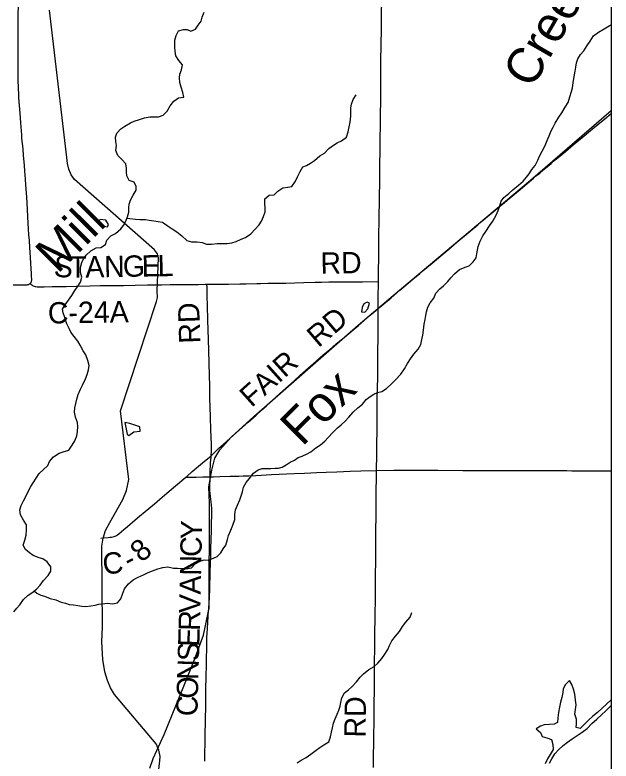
# Model space of a CAD drawing. Extents: x -87 to 2145, y -2128 to 440.
# Drawn here: x 188.3 to 230.2, y -1010.1 to -957.6 of the extents above; entities that cross this region are included whole.
import ezdxf

# ---------------------------------------------------------------- set-up
doc = ezdxf.new("R2010")
doc.units = 0
for name, color, linetype in [('GM_X_County_Road', 7, 'Continuous'), ('GM_X_County_Road_Text', 7, 'Continuous'), ('GM_X_Minor_Lake', 7, 'Continuous'), ('GM_X_Minor_River', 7, 'Continuous'), ('GM_X_Minor_River_Text', 7, 'Continuous'), ('GM_X_Rail_Line', 7, 'Continuous'), ('GM_X_Township_Road', 7, 'Continuous'), ('SC_Scratch1', 7, 'Continuous')]:
    doc.layers.add(name, color=color, linetype=linetype)

msp = doc.modelspace()

# ---------------------------------------------------------------- linework, layer by layer
at = {"layer": 'GM_X_County_Road'}
msp.add_line((201.805, -988.806), (202.068, -988.593), dxfattribs=at)
for points in [[(188.544, -963.408), (188.537, -963.299), (188.505, -962.628), (188.492, -962.268), (188.484, -961.793), (188.484, -960.76), (188.485, -960.186), (188.486, -959.497), (188.49, -958.825), (188.499, -957.955), (188.525, -956.578), (188.537, -955.659), (188.538, -955.627)], [(189.333, -976.48), (189.354, -976.459), (189.377, -976.432), (189.398, -976.405), (189.414, -976.374), (189.426, -976.344), (189.434, -976.311), (189.438, -976.284), (189.44, -976.25), (189.441, -976.213), (189.441, -976.158), (189.439, -976.004), (189.429, -975.765), (189.383, -975.076), (189.354, -974.619), (189.314, -973.947), (189.276, -973.456), (189.246, -973.047), (189.222, -972.622), (189.201, -972.246), (189.175, -971.771), (189.119, -970.804), (189.094, -970.411), (189.056, -969.806), (189.037, -969.544), (189.006, -969.135), (188.958, -968.563), (188.925, -968.187), (188.87, -967.451), (188.837, -967.042), (188.811, -966.797), (188.778, -966.471), (188.758, -966.259), (188.74, -966.014), (188.674, -965.164), (188.621, -964.493), (188.583, -963.954), (188.544, -963.408)], [(213.812, -978.237), (213.915, -978.151), (214.343, -977.793), (214.443, -977.709), (214.718, -977.475), (215.338, -976.938), (215.602, -976.718), (216.251, -976.165), (216.731, -975.768), (216.97, -975.568), (217.603, -975.046), (218.205, -974.539), (218.766, -974.059), (219.346, -973.577), (219.734, -973.248), (220.817, -972.346), (221.079, -972.123), (221.625, -971.651), (221.889, -971.43), (222.208, -971.173), (222.693, -970.782), (222.881, -970.624), (223.146, -970.404), (223.535, -970.077), (223.786, -969.867), (224.149, -969.559), (224.726, -969.074), (224.95, -968.882), (225.164, -968.703), (225.464, -968.447), (225.964, -968.023), (226.254, -967.783), (226.582, -967.51), (226.971, -967.183), (227.529, -966.725), (228.161, -966.202), (228.877, -965.601), (229.242, -965.297), (229.738, -964.893), (230.183, -964.524)], [(188.147, -976.569), (188.443, -976.566), (188.77, -976.571), (188.985, -976.573), (189.033, -976.572), (189.083, -976.569), (189.132, -976.563), (189.173, -976.557), (189.21, -976.549), (189.241, -976.538), (189.272, -976.524), (189.299, -976.508), (189.333, -976.48)], [(189.333, -976.48), (189.39, -976.529), (189.446, -976.577), (189.5, -976.614), (189.554, -976.641), (189.611, -976.663), (189.679, -976.683), (189.736, -976.694), (189.819, -976.705), (189.985, -976.714), (190.314, -976.712), (190.889, -976.697), (191.478, -976.685), (191.856, -976.677), (192.56, -976.654), (193.545, -976.638), (194.25, -976.625), (195.102, -976.617), (195.906, -976.606), (196.725, -976.594), (197.594, -976.577), (198.02, -976.569), (198.578, -976.564), (199.169, -976.551), (200.232, -976.548), (201.168, -976.541), (201.643, -976.534), (201.766, -976.533)], [(201.766, -976.533), (201.938, -976.531), (203.07, -976.515), (203.283, -976.514), (204.087, -976.506), (204.513, -976.496), (205.266, -976.477), (205.528, -976.472), (206.037, -976.462), (207.316, -976.442), (207.923, -976.432), (208.579, -976.416), (209.379, -976.389), (209.823, -976.375), (210.332, -976.368), (211.168, -976.369), (211.726, -976.367), (212.021, -976.364), (212.71, -976.35), (213.834, -976.338)], [(202.068, -988.593), (202.079, -988.241), (202.076, -987.785), (202.039, -986.769), (202.02, -985.883), (201.997, -985.162), (201.98, -984.555), (201.96, -983.653), (201.944, -982.964), (201.918, -982.056), (201.89, -981.197), (201.869, -980.409), (201.831, -979.064), (201.802, -978.015), (201.782, -977.359), (201.77, -976.732), (201.766, -976.533)], [(213.812, -978.237), (213.809, -977.884), (213.812, -977.556), (213.834, -976.338)], [(202.068, -988.593), (202.179, -988.486), (202.438, -988.215), (202.602, -988.056), (202.896, -987.795), (203.398, -987.348), (204.026, -986.795), (204.654, -986.242), (205.216, -985.738), (205.607, -985.388), (205.961, -985.071), (206.35, -984.718), (206.898, -984.224), (207.505, -983.673), (207.924, -983.305), (208.32, -982.935), (208.904, -982.409), (209.448, -981.934), (209.944, -981.505), (210.379, -981.131), (210.856, -980.73), (211.43, -980.24), (212.049, -979.729), (212.417, -979.426), (213.252, -978.712), (213.501, -978.499), (213.812, -978.237)], [(213.693, -989.623), (213.703, -988.492), (213.717, -987.672), (213.727, -986.934), (213.728, -986.442), (213.729, -986.049), (213.729, -985.492), (213.737, -985.001), (213.743, -984.542), (213.755, -983.902), (213.778, -983), (213.784, -982.344), (213.784, -981.491), (213.788, -981.032), (213.796, -980.492), (213.803, -979.983), (213.804, -979.508), (213.807, -979.131), (213.812, -978.237)], [(200.291, -990.095), (200.34, -990.054), (200.737, -989.712), (201.167, -989.333), (201.582, -988.986), (201.805, -988.806)], [(201.99, -990.075), (202, -989.603), (202.012, -989.277), (202.027, -989.081), (202.047, -988.886), (202.059, -988.725), (202.068, -988.593)], [(213.48, -1010.519), (213.489, -1009.748), (213.504, -1008.732), (213.511, -1008.098), (213.518, -1007.452), (213.534, -1005.992), (213.537, -1005.123), (213.55, -1003.582), (213.557, -1003.122), (213.573, -1002.138), (213.579, -1001.105), (213.589, -999.99), (213.608, -998.448), (213.617, -997.267), (213.635, -995.725), (213.652, -993.626), (213.659, -993.068), (213.667, -992.396), (213.675, -991.576), (213.693, -989.623)], [(194.312, -994.385), (194.458, -994.373), (194.815, -994.34), (194.943, -994.325), (195.065, -994.309), (195.149, -994.292), (195.23, -994.27), (195.303, -994.242), (195.408, -994.194), (195.479, -994.153), (195.558, -994.095), (195.757, -993.923), (195.919, -993.786), (196.182, -993.563), (196.718, -993.106), (197.02, -992.854), (197.422, -992.517), (198.074, -991.968), (198.464, -991.643), (198.955, -991.233), (199.561, -990.707), (200.291, -990.095)], [(201.608, -1010.075), (201.625, -1009.321), (201.63, -1009.009), (201.638, -1008.55), (201.651, -1007.96), (201.654, -1007.533), (201.661, -1007.041), (201.676, -1006.304), (201.688, -1005.723), (201.691, -1005.615), (201.698, -1005.205), (201.722, -1003.959), (201.74, -1003.451), (201.741, -1003.09), (201.742, -1002.729), (201.746, -1002.275), (201.754, -1001.851), (201.769, -1001.46), (201.791, -1001.002), (201.799, -1000.821), (201.807, -1000.625), (201.817, -1000.428), (201.861, -999.804), (201.894, -999.307), (201.919, -998.975), (201.94, -998.58), (201.964, -997.912), (201.996, -996.812), (202.02, -996.156), (202.031, -995.598), (202.042, -995.041), (202.059, -994.549), (202.082, -993.779), (202.095, -993.198), (202.099, -992.942), (202.107, -992.523), (202.103, -992.293), (202.09, -992.07), (202.066, -991.844), (202.016, -991.468), (201.993, -991.24), (201.979, -991.012), (201.974, -990.734), (201.988, -990.21), (201.99, -990.075)]]:
    msp.add_lwpolyline(points, dxfattribs=at)
at = {"layer": 'GM_X_Minor_Lake'}
for points in [[(194.646, -972.032), (194.248, -971.964), (194.049, -972.208), (194.432, -972.424)], [(194.432, -972.424), (194.771, -972.496), (194.837, -972.327), (194.646, -972.032)], [(213.072, -978.249), (213.206, -977.871), (213.038, -977.795), (212.793, -977.917), (212.674, -978.164)], [(212.674, -978.164), (212.623, -978.464), (212.874, -978.483), (213.072, -978.249)], [(195.986, -986.266), (196.164, -987.083), (196.282, -987.158), (196.622, -986.908), (197.058, -986.874)], [(197.058, -986.874), (197.055, -986.561), (196.351, -986.325), (195.986, -986.266)], [(230.183, -1005.77), (230.175, -1005.777), (229.874, -1006.038), (229.562, -1006.359), (229.24, -1006.659), (228.91, -1006.909), (228.599, -1007.2), (228.349, -1007.463), (228.007, -1007.773), (227.738, -1007.713), (227.757, -1007.462), (227.759, -1007.12), (227.631, -1006.763), (227.693, -1006.433), (227.724, -1006.122), (227.676, -1005.778), (227.631, -1005.354), (227.533, -1005.009), (227.414, -1004.682), (227.253, -1004.415), (226.972, -1004.677), (226.811, -1004.993), (226.782, -1005.243), (226.719, -1005.603), (226.637, -1005.933), (226.554, -1006.282), (226.481, -1006.662), (226.448, -1007.033), (226.426, -1007.354), (226.171, -1007.486), (225.85, -1007.495), (225.477, -1007.522), (225.223, -1007.613), (224.926, -1007.804), (225.228, -1008.056), (225.348, -1008.352), (225.666, -1008.444), (225.993, -1008.556), (226.081, -1008.902), (226.118, -1009.265), (225.905, -1009.61), (225.714, -1009.905), (225.541, -1010.271)], [(225.844, -1010.221), (226.015, -1009.906), (226.238, -1009.571), (226.489, -1009.278), (226.811, -1008.968), (227.13, -1008.748), (227.459, -1008.518), (227.789, -1008.278), (228.149, -1008.029), (228.499, -1007.77), (228.842, -1007.44), (229.174, -1007.12), (229.506, -1006.82), (229.807, -1006.539), (230.077, -1006.277), (230.183, -1006.167)]]:
    msp.add_lwpolyline(points, dxfattribs=at)
at = {"layer": 'GM_X_Minor_River'}
for points in [[(197.691, -1016.369), (198.446, -1010.055), (198.467, -1009.744), (198.372, -1009.308), (198.197, -1008.859), (195.258, -1005.391), (194.994, -1004.919), (194.761, -1004.407), (194.582, -1003.797), (194.452, -1002.926), (194.365, -1001.685), (194.423, -1000.62), (194.371, -994.961), (194.462, -994.38), (194.632, -993.843), (194.942, -993.3), (195.862, -991.663), (196.115, -991.027), (196.273, -990.258), (195.68, -985.445), (198.209, -977.744), (198.279, -977.455), (198.276, -976.981), (198.357, -974.659), (198.287, -974.384), (198.076, -974.105), (192.45, -969.161), (192.21, -968.84), (192.054, -968.442), (191.968, -968.026), (191.922, -967.612), (190.702, -957.239)], [(192.884, -983.905), (193.005, -983.617), (193.22, -983.192), (193.332, -982.874), (193.433, -982.555), (193.474, -982.245), (193.386, -981.899), (193.26, -981.502), (193.06, -981.203), (192.862, -980.823), (192.682, -980.525), (192.423, -980.193), (192.203, -979.894), (192.081, -979.638), (191.922, -979.32), (191.777, -978.872), (191.648, -978.535), (191.607, -978.271), (191.798, -977.976), (192.041, -977.653), (192.273, -977.329), (192.486, -976.974), (192.656, -976.699), (192.878, -976.384), (192.971, -976.035), (192.872, -975.71), (192.884, -975.358), (192.967, -975.008), (193.076, -974.751), (193.276, -974.476), (193.598, -974.185), (193.967, -973.967), (194.299, -973.939), (194.637, -973.74), (194.728, -973.431), (195.01, -973.129), (195.337, -972.949), (195.709, -972.641), (195.909, -972.386), (196.048, -972.129), (196.181, -971.792), (196.282, -971.463), (196.264, -971.141), (196.293, -970.89), (196.383, -970.611), (196.566, -970.255), (196.798, -969.922), (196.798, -969.65), (196.658, -969.353), (196.301, -969.229), (196.132, -968.901), (196.112, -968.618), (196.1, -968.366), (196.071, -968.053), (195.791, -967.751), (195.5, -967.469), (195.351, -967.121), (195.414, -966.771), (195.363, -966.497), (195.334, -966.184), (195.434, -965.906), (195.716, -965.594), (195.984, -965.412), (196.383, -965.185), (196.648, -965.064), (197.014, -964.946), (197.379, -964.828), (197.743, -964.741), (198.094, -964.763), (198.355, -964.743), (198.69, -964.634), (198.961, -964.362), (199.185, -963.977), (199.447, -963.654), (199.767, -963.404), (200.13, -963.357), (200.071, -963.033), (199.953, -962.676), (199.865, -962.331), (199.826, -962.007), (199.855, -961.756), (199.987, -961.439), (200.049, -961.099), (199.779, -960.797), (199.569, -960.468), (199.521, -960.124), (199.51, -959.871), (199.499, -959.609), (199.518, -959.348), (199.6, -959.019), (199.772, -958.703), (200.117, -958.605), (200.377, -958.614), (200.634, -958.724), (200.961, -958.575), (201.151, -958.31), (201.351, -958.025), (201.422, -957.735), (201.565, -957.378)], [(216.614, -981.104), (216.797, -980.758), (216.88, -980.409), (216.95, -980.12), (217.003, -979.769), (217.048, -979.338), (217.119, -979.018), (217.159, -978.738), (217.209, -978.478), (217.29, -978.149), (217.452, -977.832), (217.715, -977.5), (217.867, -977.153), (218.149, -976.841), (218.408, -976.629), (218.709, -976.337), (218.909, -976.073), (219.18, -975.791), (219.521, -975.501), (219.919, -975.324), (220.213, -975.234), (220.484, -974.941), (220.704, -974.678), (220.744, -974.397), (220.794, -974.127), (220.843, -973.867), (220.976, -973.509), (221.17, -973.134), (221.382, -972.809), (221.637, -972.416), (221.869, -972.082), (222.114, -971.678), (222.246, -971.34), (222.358, -971.022), (222.46, -970.694), (222.64, -970.428), (222.991, -970.139), (223.281, -969.898), (223.674, -969.559), (223.994, -969.289), (224.225, -969.005), (224.425, -968.751), (224.616, -968.446), (224.836, -968.182), (225.04, -967.806), (225.15, -967.519), (225.344, -967.163), (225.538, -966.777), (225.701, -966.421), (225.823, -966.093), (225.976, -965.736), (226.106, -965.469), (226.256, -965.192), (226.502, -964.768), (226.723, -964.464), (226.967, -964.08), (227.16, -963.745), (227.274, -963.346), (227.397, -962.978), (227.467, -962.719), (227.509, -962.368), (227.571, -962.048), (227.648, -961.548), (227.699, -961.248), (227.75, -960.947), (227.84, -960.679), (228.031, -960.374), (228.261, -960.1), (228.505, -959.726), (228.707, -959.421), (228.95, -959.057), (229.301, -958.788), (229.691, -958.55), (230.058, -958.362), (230.183, -958.28)], [(196.149, -971.873), (196.337, -971.898), (196.737, -971.943), (197.057, -971.964), (197.448, -971.978), (197.708, -972.018), (198.027, -972.06), (198.347, -972.112), (198.636, -972.172), (198.969, -972.406), (199.312, -972.629), (199.656, -972.843), (200.007, -973.118), (200.347, -973.452), (200.675, -973.544), (201.086, -973.539), (201.425, -973.602), (201.723, -973.703), (202.093, -973.716), (202.476, -973.67), (202.838, -973.672), (203.189, -973.655), (203.522, -973.607), (203.816, -973.527), (204.183, -973.369), (204.478, -973.248), (204.859, -972.98), (205.141, -972.668), (205.443, -972.357), (205.603, -972.081), (205.744, -971.774), (205.856, -971.436), (205.857, -971.133), (205.846, -970.881), (205.828, -970.528), (206.138, -970.268), (206.491, -970.24), (206.751, -969.978), (207.1, -969.749), (207.463, -969.701), (207.726, -969.65), (208, -969.278), (208.141, -968.961), (208.315, -968.594), (208.507, -968.259), (208.761, -968.168), (209.048, -968.007), (209.325, -967.825), (209.708, -967.507), (210.036, -967.297), (210.348, -966.976), (210.658, -966.746), (210.914, -966.574), (211.23, -966.434), (211.571, -966.175), (211.694, -965.797), (211.777, -965.457), (211.839, -965.117), (211.873, -964.706), (211.873, -964.424), (211.894, -964.112), (211.933, -963.852), (212.045, -963.534), (212.247, -963.209)], [(189.627, -998.087), (189.81, -998.27), (190.096, -998.401), (190.354, -998.481), (190.74, -998.635), (191.128, -998.72), (191.524, -998.885), (191.822, -998.966), (192.08, -999.046), (192.38, -999.087), (192.68, -999.118), (192.969, -999.179), (193.259, -999.189), (193.611, -999.162), (193.904, -999.102), (194.168, -999.041), (194.42, -998.999), (194.752, -998.961), (195.132, -999.005), (195.486, -998.937), (195.706, -998.663), (195.828, -998.325), (195.962, -997.948), (196.245, -997.595), (196.566, -997.315), (196.893, -997.156), (197.301, -996.959), (197.638, -996.81), (197.943, -996.68), (198.309, -996.552), (198.674, -996.445), (199.026, -996.417), (199.424, -996.512), (199.705, -996.512), (200.047, -996.514), (200.418, -996.518), (200.69, -996.467), (200.931, -996.194), (201.279, -996.005), (201.563, -995.904), (201.843, -995.935), (202.229, -995.808), (202.494, -995.676), (202.734, -995.423), (202.905, -995.137), (203.095, -994.872), (203.219, -994.474), (203.288, -994.215), (203.443, -993.828), (203.596, -993.471), (203.72, -993.073), (203.732, -992.731), (203.784, -992.391), (203.906, -992.063), (204.069, -991.706), (204.18, -991.408), (204.26, -991.129), (204.332, -990.8), (204.524, -990.464), (204.734, -990.21), (205.038, -989.829), (205.378, -989.589), (205.642, -989.488), (205.893, -989.487), (206.265, -989.48), (206.556, -989.47), (206.807, -989.469), (207.06, -989.408), (207.347, -989.237), (207.614, -989.055), (207.911, -988.895), (208.178, -988.723), (208.463, -988.613), (208.81, -988.454), (209.065, -988.312), (209.416, -988.043), (209.755, -987.834), (210.045, -987.562), (210.285, -987.309), (210.618, -986.959), (210.941, -986.628), (211.199, -986.416), (211.48, -986.154), (211.75, -985.872), (212.054, -985.521), (212.375, -985.23), (212.715, -984.971), (212.958, -984.647), (213.236, -984.426), (213.493, -984.264), (213.758, -984.152), (214.072, -984.063), (214.4, -983.863), (214.733, -983.533), (215.024, -983.252), (215.389, -982.852), (215.653, -982.469), (215.857, -982.094), (216.069, -981.779), (216.311, -981.446), (216.614, -981.104)], [(188.188, -999.58), (188.388, -999.326), (188.607, -999.072), (188.861, -998.699), (189.193, -998.399), (189.45, -998.227), (189.78, -997.967), (190.04, -997.694), (190.262, -997.38), (190.606, -997.02), (190.778, -996.704), (190.778, -996.402), (190.54, -996.061), (190.236, -995.849), (189.968, -995.769), (189.552, -995.603), (189.278, -995.422), (188.995, -995.18), (188.845, -994.893), (188.958, -994.525), (189.06, -994.186), (189.084, -993.804), (189.086, -993.462), (188.877, -993.122), (188.659, -992.752), (188.602, -992.388), (188.702, -992.099), (188.875, -991.763), (189.036, -991.467), (189.199, -991.101), (189.391, -990.765), (189.551, -990.499), (189.754, -990.164), (189.976, -989.85), (190.256, -989.578), (190.568, -989.277), (190.698, -989), (190.97, -988.668), (191.371, -988.42), (191.655, -988.32), (192.051, -988.193), (192.284, -987.839), (192.475, -987.534), (192.608, -987.197), (192.669, -986.887), (192.681, -986.535), (192.671, -986.253), (192.514, -985.874), (192.446, -985.52), (192.466, -985.228), (192.537, -984.919), (192.618, -984.62), (192.7, -984.281), (192.884, -983.905)], [(211.717, -1005.057), (211.986, -1004.825), (212.288, -1004.504), (212.54, -1004.18), (212.77, -1003.927), (213.142, -1003.628), (213.521, -1003.41), (213.78, -1003.188), (214.072, -1002.856), (214.273, -1002.562), (214.486, -1002.217), (214.606, -1001.94), (214.768, -1001.623), (215.03, -1001.29), (215.303, -1000.948), (215.526, -1000.604), (215.758, -1000.29), (216.051, -999.948), (216.183, -999.621)], [(208.114, -1010.191), (208.391, -1010.01), (208.75, -1009.812), (209.078, -1009.592), (209.45, -1009.313), (209.707, -1009.121), (209.985, -1008.93), (210.344, -1008.711), (210.456, -1008.363), (210.528, -1008.044), (210.599, -1007.744), (210.67, -1007.415), (210.772, -1007.106), (210.924, -1006.77), (211.034, -1006.502), (211.134, -1006.213), (211.183, -1005.953), (211.246, -1005.614), (211.448, -1005.269), (211.717, -1005.057)]]:
    msp.add_lwpolyline(points, dxfattribs=at)
at = {"layer": 'GM_X_Rail_Line'}
msp.add_lwpolyline([(197.758, -1010.567), (197.975, -1009.888), (198.759, -1008.214), (200.145, -1004.81), (200.881, -1002.93), (201.512, -1001.219), (201.915, -999.311), (201.947, -991.924), (201.887, -990.775), (202.11, -989.608), (202.328, -988.757), (202.675, -988.171), (203.476, -987.295), (205.067, -985.833), (212.409, -979.406), (214.858, -977.33), (224.526, -969.206), (230.183, -964.298)], dxfattribs=at)
at = {"layer": 'GM_X_Township_Road'}
for points in [[(213.984, -963.146), (213.993, -961.828), (214.004, -960.926), (214.026, -959.598), (214.035, -958.679), (214.05, -957.465), (214.058, -956.645), (214.073, -955.697)], [(213.834, -976.338), (213.838, -975.736), (213.843, -974.539), (213.859, -973.374), (213.88, -971.734), (213.892, -970.684), (213.916, -969.028), (213.932, -967.863), (213.936, -967.388), (213.944, -966.732), (213.955, -966.043), (213.965, -965.568), (213.968, -964.764), (213.982, -963.435), (213.984, -963.146)], [(201.99, -990.075), (202.229, -990.072), (202.663, -990.053), (203.408, -990.03), (203.723, -990.025), (204.017, -990.022), (204.312, -990.016), (204.722, -990.002), (205.197, -989.981), (206.31, -989.908), (206.85, -989.881), (207.358, -989.867), (207.898, -989.843), (208.617, -989.816), (209.075, -989.8), (209.501, -989.782), (210.14, -989.758), (210.894, -989.723), (211.845, -989.688), (212.582, -989.656), (213.693, -989.623)], [(213.693, -989.623), (214.91, -989.614), (215.812, -989.615), (216.533, -989.617), (217.238, -989.616), (218.009, -989.618), (219.764, -989.625), (220.814, -989.627), (221.585, -989.629), (222.569, -989.63), (223.586, -989.634), (225.095, -989.639), (226.013, -989.641), (226.669, -989.641), (227.063, -989.642), (227.423, -989.645), (228.145, -989.648), (228.834, -989.653), (229.982, -989.658), (230.183, -989.659)], [(200.291, -990.095), (201.014, -990.093), (201.478, -990.084), (201.99, -990.075)]]:
    msp.add_lwpolyline(points, dxfattribs=at)
at = {"layer": 'SC_Scratch1'}
msp.add_lwpolyline([(-21.617, -825.188), (230.183, -825.188), (230.183, -1245.188), (-21.617, -1245.188)], close=True, dxfattribs=at)

# ---------------------------------------------------------------- texts
at = {"layer": 'GM_X_County_Road_Text'}
for s, rotation, p in [('S', 356.4652, (190.963, -975.996)), ('T', 0.1837, (192.079, -976.061)), ('A', 0.9632, (193.224, -976.058)), ('N', 0.9697, (194.544, -976.035)), ('G', 0.969, (195.863, -976.013)), ('E', 0.9686, (197.183, -975.991)), ('L', 0.9706, (198.305, -975.972)), ('RD', 0.9912, (209.759, -975.795)), ('C-24A', 1.005, (190.59, -979.299)), ('RD', 91.9555, (201.309, -980.68)), ('RD', 40.4948, (209.603, -981.03)), ('FAIR', 41.9218, (204.904, -985.244)), ('Y', 88.828, (201.407, -994.492)), ('8', 40.96, (197.176, -996.149)), ('C', 88.8251, (201.382, -995.724)), ('C', 6.0846, (194.506, -996.959)), ('-', 27.735, (196.32, -996.649)), ('N', 88.8289, (201.355, -997.044)), ('A', 88.8148, (201.327, -998.364)), ('V', 88.6356, (201.296, -999.689)), ('R', 88.4, (201.261, -1000.927)), ('E', 88.3455, (201.229, -1002.05)), ('S', 88.3491, (201.199, -1003.062)), ('N', 88.3476, (201.161, -1004.381)), ('O', 88.3459, (201.123, -1005.701)), ('C', 88.3488, (201.088, -1006.932)), ('RD', 89.5113, (212.924, -1008.42))]:
    msp.add_text(s, height=1.5, rotation=rotation, dxfattribs=at).set_placement(p)
at = {"layer": 'GM_X_Minor_River_Text'}
for s, height, rotation, p in [('Creek', 2.4994, 60.0109, (224.622, -962.841)), ('Mill', 2.4995, 45.0075, (191.264, -975.851)), ('Fox', 2.4995, 45.0076, (208.47, -987.99))]:
    msp.add_text(s, height=height, rotation=rotation, dxfattribs=at).set_placement(p)

doc.saveas('drawing.dxf')
